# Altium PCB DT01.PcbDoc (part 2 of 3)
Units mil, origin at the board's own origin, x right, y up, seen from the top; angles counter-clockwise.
Board outline 2134.7 x 2226.1 mil, 2 copper layers (Top Layer, Bottom Layer), stack 57.918 mil thick; 95 components, 87 nets, 468 pads, 300 vias.
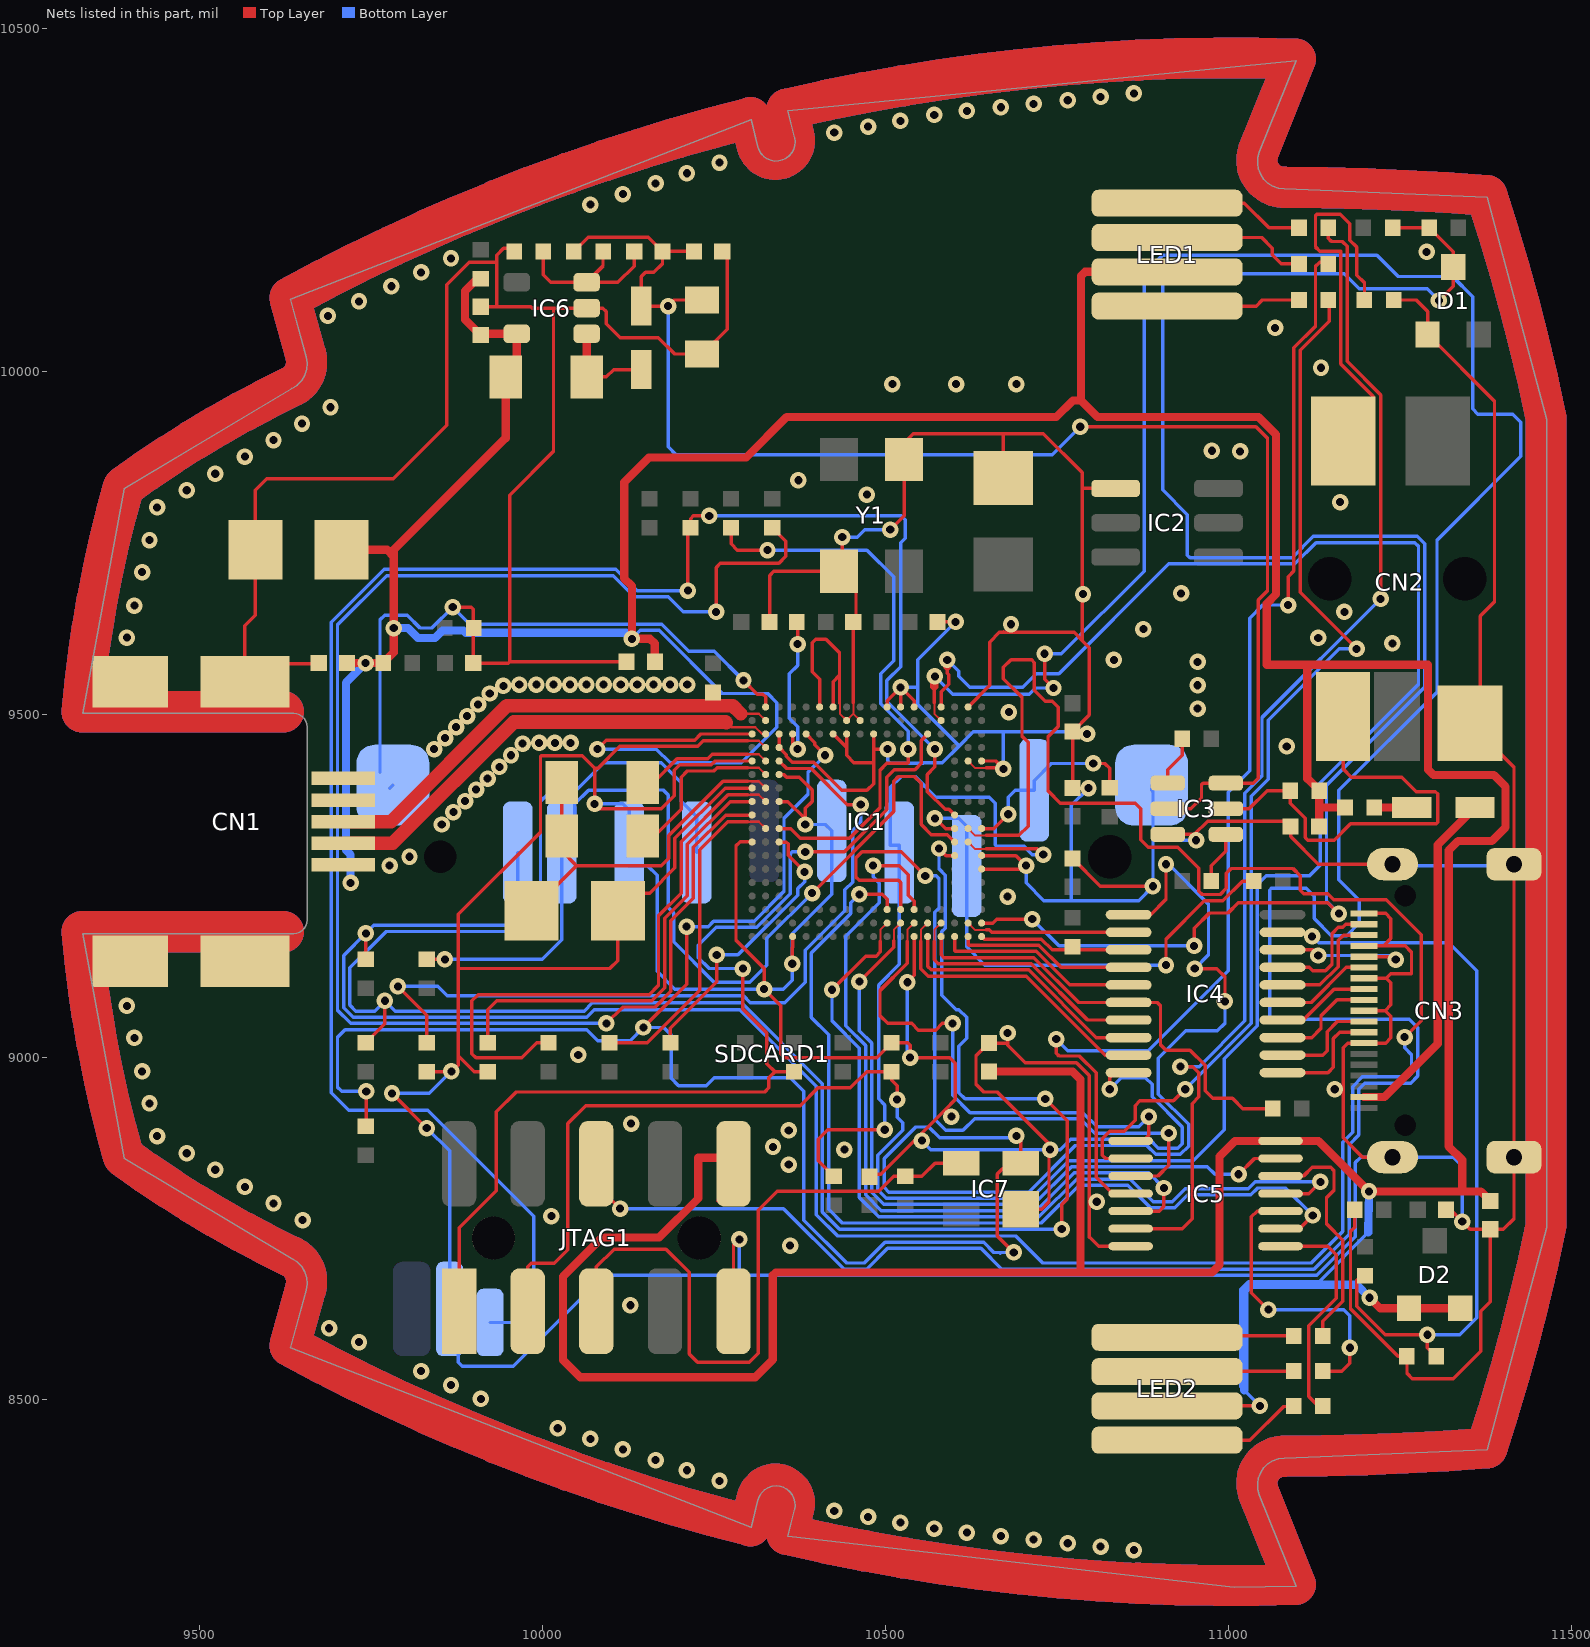
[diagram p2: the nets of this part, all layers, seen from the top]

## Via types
v1: diameter 24, hole 11.81, Top Layer to Bottom Layer, tented both sides, 295 vias
v2: diameter 24.02, hole 11.81, Top Layer to Bottom Layer, tented both sides, 5 vias

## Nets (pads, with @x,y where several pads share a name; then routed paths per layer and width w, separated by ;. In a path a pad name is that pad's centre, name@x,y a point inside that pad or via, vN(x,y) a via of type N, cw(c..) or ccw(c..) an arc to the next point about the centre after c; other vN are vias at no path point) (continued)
5V0: C15.2 C16.2 C17.2 C18.2 C19.1 C20.1 C21.1 CN1.1 D2.1 D2.2 IC1.T18 IC5.14 IC6.5 JTAG1.10 L3.1 LED1.A LED2.A R18.2 R20.2 R37.1 R42.1 | length 9669.8
  Top Layer w5: CN1.1@9709.36,9280.11 CN1.1@9710.34,9279.12 ; C18.2@9713.01,9572.3 C18.2@9715.04,9574.34 ; R42.1@9909.38,10134.7 R42.1@9909.87,10134.7 ; C15.2@9909.67,10052.76 C15.2@9909.87,10052.56 ; v1(10080.01,9449.02) 10093.01,9462.02 10222.01,9462.02 10230.91,9470.92 IC1.T18@10305.52,9470.92 ; JTAG1.10@10255.25,8790.07 10278.38,8813.21 JTAG1.10@10278.38,8844.21 10278.38,8849.02 JTAG1.10@10278.39,8900.76 ; JTAG1.10@10270.01,8790.07 JTAG1.10@10278.38,8798.45 ; LED2.A@10910.6,8491.32 v1(11045.79,8491.32) ; C20.1@11132,9336.21 11132.51,9336.72 11132.51,9363.74 ; 11132.53,9363.76 R20.2@11132.53,9388.34
  Top Layer w12: C19.1@9707.18,9739.65 9773.15,9739.65 9783.01,9729.79 ; C18.2@9715.04,9574.34 v1(9742,9574.34) R18.2@9767.66,9574.34 9783.01,9589.69 v1@9783.01,9625 ; v1(9783.01,9625.49) 9783.01,9729.79 ; R42.1@9909.38,10134.7 9904.69,10134.7 9887.01,10117.02 9887.01,10075.02 9909.47,10052.56 9909.67,10052.76 9911.44,10054.53 IC6.5@9962.36,10054.53 9962.36,10007.65 L3.1@9946.26,9991.56 9946.27,9902.28 9783.01,9739.02 9783.01,9729.79 ; C21.1@10163.75,9576.31 10163.75,9602.85 10156.85,9609.74 v1(10130.28,9609.74) 10130.28,9686.72 10119,9698 10119,9838 10155,9874 10297,9874 10356,9933 10749,9933 10773.23,9957.23 10785,9957.23 ; JTAG1.10@10278.38,8844.21 JTAG1.10@10269.59,8853 ; JTAG1.10@10278.39,8849.02 10274.4,8853 JTAG1.10@10269.59,8853 ; C16.2@10650.82,8979.01 10772.99,8979.01 10784.51,8967.49 10784.51,8686.49 ; LED1.A@10910.6,10144.87 10790.87,10144.87 10785,10139 10785,9957.23 ; C20.1@11132,9336.21 11132.51,9336.72 11132.51,9363.74 ; 11132.51,9363.78 R20.2@11132.51,9388.36 11115,9405.88 11115,9572 ; 11132.53,9363.76 11132.77,9364 R37.1@11169.99,9364 ; v1(11206,8649) 11221.41,8633.59 D2.1@11263.33,8633.59 D2.2@11338.13,8633.59 ; 11341,8805 11341,8850 11321.19,8869.81 11321.19,9301.19 11335,9315 11384,9315 11403.86,9334.86 11403.86,9394.14 11387,9411 11299,9411 11291,9419 11291,9572 11115,9572 ; C17.2@11381.93,8790.08 11368.01,8804 v1(11205,8804) 11131.34,8877.66 IC5.14@11075.97,8877.66 11009.66,8877.66 10987,8855 10987,8697 10976,8686 10340.07,8686 10335.79,8681.72 10335.79,8558.79 10310,8533 10055,8533 10030,8558 10030,8680 10087,8737 10170,8737 10227,8794 10227,8853 JTAG1.10@10269.59,8853 ; 10785,9957.23 10809.23,9933 11044,9933 11069.51,9907.49 11069.51,9674.71 11056,9661.21 11056,9572 11115,9572
  Bottom Layer w5: v1(10080.01,9449.02) 10165.73,9449.02 10185.92,9428.83 10289.9,9428.83 10341.7,9480.63 10341.7,9516.41 10328.06,9530.04 10262.26,9530.04 10170.29,9622.02 10142.55,9622.02 v1(10130.28,9609.74) ; v1(11045.79,8491.32) 11023,8514.11 11017.85,8519.26 11017.85,8661.17 11029.31,8672.63 11132.23,8672.63 11203.82,8744.22
  Bottom Layer w12: v1(9720,9254) 9720,9295 9713.5,9301.5 9713.5,9545.84 v1(9742,9574.34) ; v1(9783.01,9625.49) 9803.63,9625.49 9818.11,9611 9842.98,9611 9854,9622.02 9884.63,9622.02 9888.13,9618.52 10121.51,9618.52 v1(10130.28,9609.74) ; 11023,8514.11 11023,8659 11032,8668 11187,8668 v1(11206,8649) ; 11203.82,8744.22 v1(11205,8804)
12V: C4.2 C5.2 C6.2 D4.2 IC3.2 IC3.6 R40.2 | length 2174.7
  Top Layer w5: R40.2@10045.81,10174.58 10066.45,10195.22 10154.25,10195.22 C6.2@10174.89,10174.58 ; C5.2@10222.94,10174.58 C5.2@10220.81,10174.58 C6.2@10174.89,10174.58 ; C4.2@10232.62,10103.74 10191.86,10103.74 v1(10183.01,10094.89) D4.2@10144.06,10094.89 10144.06,10138 10150.06,10144 10162,10144 10174.89,10156.89 C6.2@10174.89,10174.58 ; v1(10784.01,9919.02) 11040.28,9919.02 11057.01,9902.29 11057.01,9679.89 11043.5,9666.38 11043.5,9406.52 11036,9399.02 IC3.6@10996.58,9399.02 ; IC3.2@10895.97,9361.98 IC3.2@10911.57,9361.98 10945.24,9361.98 10960.78,9377.52 10960.78,9397.16 10963.01,9399.39 IC3.6@10996.22,9399.39
  Bottom Layer w5: v1@10181.45,10093.33 v1(10183.01,10094.89) 10183.01,9889.61 10194.6,9878.02 10743.01,9878.02 v1(10784.01,9919.02)
CARD_DET: IC1.K3 R22.1 SDCARD1.SW3 | length 2746.8
  Top Layer w5: v1(10212.01,9680.02) 10212.01,9767.72 R22.1@10215.89,9771.61 10215.89,9784.9 10220.01,9789.02 v1(10243.01,9789.02) ; v1(10572.01,9449.02) 10572.01,9422.96 10561.01,9411.96 10561.01,9387.02 10587.01,9361.02 10592.59,9361.02 IC1.K3@10600.8,9352.81
  Bottom Layer w5: SDCARD1.SW3@9923.5,8612.95 9968.9,8612.95 9987.01,8631.05 9987.01,8768.03 9832.52,8922.52 9717.2,8922.52 9692,8947.72 9692,9634.14 9768.88,9711.02 10106.7,9711.02 10137.7,9680.02 v1(10212.01,9680.02) ; v1(10243.01,9789.02) 10523.01,9789.02 10528.8,9783.22 10528.8,9756.36 10522.01,9749.57 10522.01,9569.02 10502.01,9549.02 10502.01,9519.02 v1(10572.01,9449.02)
D+: CN1.3 IC1.U17 R16.1 | length 688.2
  Top Layer w3: 10295.71,9500.5 10315.32,9500.5 IC1.U17@10325.21,9490.61
  Top Layer w20: CN1.3@9709.38,9343.1 9779.01,9343.1 9948.24,9512.33 10248.36,9512.33 10277.12,9512.33 10288.95,9500.5
D-: CN1.2 IC1.T17 | length 698.2
  Top Layer w3: 10268.01,9487.5 10274.69,9480.81 10310.4,9480.81 10320.29,9470.92 IC1.T17@10325.21,9470.92 IC1.T17@10327.18,9470.92
  Top Layer w20: CN1.2@9709.38,9311.6 9781.46,9311.6 9958.18,9488.33 10267.18,9488.33 10268.01,9487.5
GND: C1.2 C2.1 C3.2 C4.1 C5.1 C7.1 C8.1 C9.1 C10.2 C11.2 C12.2 C13.2 C14.2 C15.1 C16.1 C17.1 C18.1 C19.2 C20.2 C21.2 CN1.4 CN1.5 CN1.MH1 CN1.MH2 CN1.MH3 CN1.MH4 CN2.1 CN3.1 CN3.4 CN3.7 CN3.10 CN3.13 CN3.MH1 CN3.MH2 CN3.MH3 CN3.MH4 D1.1 IC1.A6 IC1.A15 IC1.F1 IC1.G1 IC1.H18 IC1.L16 IC1.M18 IC1.N16 IC1.P1 IC1.P2 IC1.P18 IC1.R16 IC1.R17 IC1.T9 IC1.T11 IC1.T12 IC1.T16 IC1.U10 IC1.U11 IC1.V2 IC1.V6 IC1.V7 IC1.V8 IC1.V12 IC1.V13 IC1.V17 IC2.1 IC3.3 IC4.10 IC5.7 IC6.2 IC7.1 JTAG1.9 JTAG1.PEGA JTAG1.PEGB R4.2 R6.2 R15.2 R17.2 R19.2 R21.2 R32.1 R45.1 SDCARD1.3 SDCARD1.6 SDCARD1.MH1 SDCARD1.MH2 SDCARD1.SW1 Y1.2 Y1.4 | length 35773.3
  Top Layer w3: 10299.03,9461.13 10315.32,9461.13 IC1.R17@10325.21,9451.24 ; 10433.43,9515.92 10433.43,9500.5 IC1.U11@10443.27,9490.66 ; IC1.U11@10443.22,9490.61 IC1.U11@10443.27,9490.66 ; IC1.U11@10443.32,9490.61 IC1.U11@10443.27,9490.66 ; 10453.11,9516.82 10453.11,9500.5 ; IC1.U10@10463,9490.61 10453.11,9500.5 ; IC1.P2@10620.48,9431.55 10630.37,9421.66 10646.66,9421.66 ; IC1.U11@10443.27,9490.66 10453.11,9500.5
  Top Layer w5: CN1.MH3@9398.64,9139.36 9398.64,9171.02 CN1.MH4@9565.96,9171.02 ; CN1.MH2@9398.64,9546.84 9398.64,9515.02 CN1.MH1@9565.96,9515.02 ; CN1.MH4@9565.96,9139.36 CN1.MH4@9566.3,9139.02 ; C18.1@9673.7,9574.34 9673.01,9573.64 9592.77,9573.64 CN1.MH1@9565.96,9546.84 9565.97,9629.02 9581.2,9644.25 C19.2@9581.2,9739.65 9581.2,9826.2 9598,9843 9782,9843 9860,9921 9860,10126.02 9893,10159.02 9933.01,10159.02 ; v1(9780.49,8947) v1(9831.14,8896.34) ; R4.2@9831.15,8978.5 9867,8978.5 9867.5,8978.5 9877.01,8988.01 9877.01,9002.02 ; v1(9869.01,9656.02) 9896.06,9656.02 9899.05,9653.03 9899.05,9625.51 C2.1@9899.05,9574.34 9950.21,9574.34 9952.18,9576.31 ; C15.1@9909.87,10093.9 9933.01,10093.9 ; R6.2@9919.96,8978.5 9900.52,8978.5 9877.01,9002.02 ; R45.1@9958.55,10174.58 9958.55,10179.02 9943.01,10179.02 9933.01,10169.02 9933.01,10159.02 ; IC6.2@10053.01,10092.03 10016,10092.03 ; IC6.2@10064.36,10092.03 10088.01,10092.03 10093.01,10087.03 10093.01,10069.02 10113.01,10049.02 10168.66,10049.02 10192.67,10025 C4.1@10232.62,10025 10269.02,10061.4 10269.02,10167.7 C5.1@10262.15,10174.58 ; C1.2@10109.64,9213.21 10109.64,9140.4 10098.26,9129.02 9878.52,9129.02 9877.01,9130.54 ; C21.2@10122.41,9576.31 9952.18,9576.31 ; C1.2@10129.64,9239.02 10156.01,9239.02 10193.01,9276.02 10193.01,9319.02 10266.17,9392.18 IC1.M18@10305.52,9392.18 ; JTAG1.9@10278.38,8629.21 10278.38,8725.38 v1(10287,8734) ; v1(10293.01,9549.02) 10312.97,9529.06 10321.18,9529.06 10325.21,9525.02 IC1.V17@10325.21,9510.29 IC1.V17@10323.01,9510.29 ; 10299.03,9461.13 10234.12,9461.13 10226.01,9453.02 10112.8,9453.02 10080.8,9421.02 10076.01,9421.02 ; IC1.P18@10305.52,9431.55 10251.54,9431.55 10246.01,9426.02 10200.01,9426.02 10192.01,9418.02 10192.01,9381.02 10173.01,9362.02 10083.01,9362.02 v1(10076.01,9369.02) 10076.01,9421.02 ; IC1.H18@10305.52,9313.44 10303.01,9313.44 10303.01,9314.02 10288.01,9314.02 10282.01,9308.02 10282.01,9170.02 10323.01,9129.02 v1(10323.01,9099.02) 10347.01,9075.02 10347.01,9005.02 10353.01,8999.02 10487.03,8999.02 R15.2@10508.88,9020.86 10532.2,9020.86 10536.01,9017.06 v1(10536.01,8999.02) 10594.01,8999.02 10602.01,8991.02 10602.01,8938.02 10586.49,8922.51 10547.49,8883.51 10493.01,8829.02 10476.65,8829.02 C9.1@10476.65,8825.52 ; C12.2@10331.03,9634.36 10331.03,9702.03 10337.34,9708.34 Y1.2@10432.1,9708.33 10437.01,9713.24 v1(10437.01,9758.02) ; IC1.T16@10343.01,9470.92 IC1.T16@10344.89,9470.92 IC1.R16@10344.89,9451.24 ; IC1.L16@10344.89,9372.5 10357.68,9372.5 v1@10383.01,9347.17 ; IC1.N16@10344.89,9411.87 10351.85,9411.87 10355.7,9408.02 10374.32,9408.02 10393.01,9389.33 10393.01,9372.6 10383.01,9362.6 v1@10383.01,9347.17 ; IC1.R16@10344.9,9449.13 IC1.R16@10344.89,9451.24 ; v1(10364.01,9136.02) 10364.01,9159.49 ; 10364.58,9160.06 IC1.A15@10364.58,9175.65 ; v1(10383.01,9339.02) v1@10383.01,9347.17 ; IC1.V13@10403.95,9510.29 10404.01,9510.29 10404.01,9550.75 10393.01,9561.75 10393.01,9604.01 10398.14,9609.14 10413.23,9609.14 10433.01,9589.36 10433.01,9556.61 ; IC1.T12@10423.63,9469.02 10423.01,9469.02 10423.01,9470.92 IC1.T12@10423.63,9470.92 10443.32,9451.24 ; IC1.V12@10423.63,9510.29 10423.63,9547.24 10433.01,9556.61 ; 10433.01,9515.92 10433.01,9556.61 ; IC1.T11@10443.01,9470.92 IC1.T11@10443.32,9470.92 10443.32,9451.24 ; C13.2@10453.03,9634.36 10453.03,9516.9 10453.11,9516.82 ; C13.2@10457.01,9639.02 Y1.2@10457.01,9708.33 ; 10482.01,9429.02 10454.01,9429.02 10443.32,9439.71 10443.32,9451.24 ; IC1.V8@10502.01,9509.02 IC1.V8@10502.37,9509.02 ; IC1.V8@10502.37,9510.29 10502.38,9519.39 v1(10522.01,9539.02) ; v1(10503.01,9449.02) 10482.69,9449.02 ; v1(10507.01,9769.02) 10527.11,9789.12 Y1.4@10527.1,9871.33 ; IC1.V7@10522.06,9510.29 10522.06,9538.97 10541.74,9519.28 IC1.V6@10541.74,9510.29 ; Y1.4@10527.11,9895.52 10540.61,9909.02 10673.45,9909.02 ; v1(10532.01,9109.02) 10542.01,9119.02 IC1.A6@10542.01,9175.65 ; IC1.A6@10541.74,9176.13 IC1.A6@10541.98,9175.89 ; C14.2@10574.01,9632.32 C14.2@10576.04,9634.36 v1(10602.35,9634.36) ; IC1.V2@10620.48,9510.29 10652.01,9541.81 10652.01,9605.02 10666.01,9619.02 10683,9619.02 10775.01,9619.02 10787.01,9607.02 ; IC1.F1@10640.17,9274.07 10700.06,9274.07 v1(10705.01,9279.02) 10690.27,9293.76 IC1.G1@10640.17,9293.76 ; IC1.P1@10640.17,9431.55 10660.47,9431.55 v1@10670.27,9421.76 ; IC1.G1@10641.96,9291.97 IC1.G1@10643.01,9293.02 ; 10646.66,9421.66 v1@10670.36,9421.66 ; C10.2@10671.49,9843.97 10671.49,9907.06 10673.45,9909.02 ; 10672.04,9620.04 ccw(c10674.5,9622.5) 10674.5,9619.02 ; v1(10678,9035) 10678,9020.35 ; IC7.1@10697.08,8778.28 10727.58,8778.27 10738.39,8789.09 10738.39,8865 10738.39,8873.63 10663.01,8949.02 10643.01,8949.02 10632.01,8960.02 10632.01,9001.54 C16.1@10650.82,9020.35 10678,9020.35 ; C11.2@10772.84,9288.18 C11.2@10772.84,9289.49 10813.31,9249.02 v1(10890.01,9249.02) ; C8.1@10772.84,9392.31 C7.1@10772.84,9474.46 10797.01,9498.63 10797.01,9597.02 10787.01,9607.02 ; v1(10827,8953) 10827,8970 10834.17,8977.17 IC4.10@10854.51,8977.17 ; IC2.1@10835.6,9829.01 10787.01,9829.01 ; IC2.1@10835.6,9830.16 10841.71,9830.16 IC2.1@10840.56,9829.01 ; IC5.7@10857.46,8724.12 10810.88,8724.12 10798.01,8736.99 10797.01,8736.99 10797.01,8789 10797.01,8973 10778.49,8991.51 10703.5,8991.51 10678,9017.01 10678,9020.35 ; IC3.3@10916,9329.01 IC3.3@10911.57,9324.58 10950.19,9324.58 10969.63,9344.02 11082.86,9344.02 C20.2@11090.66,9336.21 11090.66,9321.5 11131,9281.16 CN3.MH4@11239.2,9281.16 ; R21.2@11184.01,8777.18 11184.01,8752.01 11178,8746 11178,8633 11247.25,8563.75 R32.1@11260.38,8563.75 11260.38,8538.62 11268,8531 11328,8531 11368,8571 11368,8629 11382,8643 C17.1@11382,8748.74 ; CN3.10@11197.86,9067.58 11228.57,9067.58 ; CN3.7@11197.86,9114.82 11230.42,9114.82 ; CN3.4@11197.86,9162.07 11226.22,9162.07 ; CN3.1@11197.86,9209.02 11193.01,9209.02 11193.01,9209.31 CN3.1@11197.86,9209.31 11229.35,9209.31 11237.01,9201.66 11237.01,9172.85 11226.22,9162.07 ; CN3.MH1@11239.2,8854 11195.48,8854 11167.5,8881.98 11167.5,8953 11167.5,9013.51 11174.32,9020.33 CN3.13@11197.86,9020.33 11229.14,9020.33 11237.01,9028.2 11237.01,9059.14 11228.57,9067.58 ; R19.2@11240.75,10103.73 11273.67,10103.73 11290.41,10086.99 D1.1@11290.41,10053.53 11388.01,9955.94 11388.01,9664.02 11367.01,9643.02 CN2.1@11367.01,9489.02 ; C3.2@11317.37,8777.18 11323.82,8777.18 v1(11341,8760) 11352.26,8748.74 C17.1@11381.93,8748.74 C17.1@11382,8748.74 ; CN2.1@11352.38,9489.02 CN2.1@11352.38,9486.71 11416.36,9422.73 CN3.MH3@11416.36,9281.16 CN3.MH2@11416.36,8854 11416.36,8764.36 11400.74,8748.74 C17.1@11382,8748.74 ; 9877.01,9002.02 9877.01,9130.54 ; 9877.01,9130.54 9877.01,9208.02 9997.01,9328.02 9997.01,9438.02 9998.01,9439.02 10058.01,9439.02 10076.01,9421.02 ; 9933.01,10093.9 9933.01,10159.02 ; 9933.01,10093.9 9983.01,10093.9 9984.87,10092.03 10016,10092.03 ; 9952.18,9576.31 9952.18,9819.18 10016,9883 10016,10092.03 ; IC1.R16@10344.89,9451.24 10355.53,9440.6 10355.53,9438.49 10364.35,9429.67 10395.35,9429.67 10436.01,9389.02 10473.01,9389.02 10482.69,9398.7 10482.69,9449.02 ; 10482.69,9449.02 IC1.T9@10482.69,9469.34 ; IC1.T9@10482.69,9469.34 IC1.T9@10482.69,9470.92 IC1.T9@10482.69,9469.34 ; 10673.45,9909.02 10730.28,9909.02 10787.01,9852.29 10787.01,9829.01 ; 10787.01,9607.02 10787.01,9675 10787.01,9829.01 ; 11226.22,9162.07 11257.93,9162.07 11267,9153 11267,9121 11266.59,9121.41 11237.01,9121.41 11230.42,9114.82 ; 11228.57,9067.58 11236.91,9075.92 11236.91,9108.34 11230.42,9114.82
  Top Layer w60: 9622,9182.61 9565.96,9182.61 9398.64,9182.61 9328.42,9182.61 ccw(c11116.51,9343.04) 9388.86,8854.97 ccw(c10303.51,10107.8) 9633.7,8708.68 cw(c9616.7,8673.17) 9654.65,8662.69 9631.51,8578.94 ccw(c11007.41,11111.18) 10303.15,8316.66 10312.86,8356.21 cw(c10339.63,8349.64) 10366.39,8343.07 10356.73,8303.7 ccw(c11007.41,11111.18) 11097.83,8230.7 11044.32,8363.83 cw(c11080.85,8378.51) 11080.68,8417.88 ccw(c11063.75,12502.73) 11376.58,8429.84 ccw(c8605.87,9343.04) 11463.13,8754.11 11463.13,8854 11463.13,9281.16 11463.13,9931.98 ccw(c8605.87,9343.04) 11376.58,10256.24 ccw(c11063.75,6183.36) 11080.68,10268.2 cw(c11080.85,10307.57) 11044.32,10322.26 11097.83,10455.38 ccw(c11007.41,7574.91) 10356.73,10382.38 10366.39,10343.02 cw(c10339.63,10336.45) 10312.86,10329.88 10303.15,10369.43 ccw(c11007.41,7574.91) 9631.51,10107.14 9654.65,10023.4 cw(c9616.7,10012.92) 9633.7,9977.41 ccw(c10303.51,8578.29) 9388.86,9831.12 ccw(c11116.51,9343.04) 9328.42,9503.48 9398.64,9503.48 9565.96,9503.48 9622,9503.48
  Bottom Layer w5: SDCARD1.MH2@9763.01,9415.18 9763.01,9637.3 9769.89,9644.18 9802.61,9644.18 9821.3,9625.49 9838.47,9625.49 v1(9869.01,9656.02) 9894.01,9631.02 10174.01,9631.02 10213.14,9591.89 10250.14,9591.89 v1(10293.01,9549.02) ; SDCARD1.MH2@9777.01,9391.64 SDCARD1.MH2@9781.77,9396.41 ; v1(9780.49,8947) 9835,8947 v1(9867,8979) ; v1(9831.14,8896.34) 9864.45,8863.04 SDCARD1.SW1@9864.45,8632.63 ; SDCARD1.SW1@9877.01,8632.63 9877.01,8555.02 9883.01,8549.02 9957.12,8549.02 10089.73,8681.63 10287,8681.63 ; v1(10076.01,9369.02) 10117.13,9369.02 10126.34,9359.81 10126.26,9359.72 SDCARD1.6@10126.26,9298.18 SDCARD1.6@10126.34,9298.27 ; SDCARD1.6@10126.26,9279.02 10153.01,9279.02 10167.01,9265.02 10167.01,9125.02 10193.01,9099.02 v1(10323.01,9099.02) 10351.18,9099.02 10364.01,9111.84 v1(10364.01,9136.02) 10364.01,9179.75 10421.54,9237.28 SDCARD1.3@10421.54,9329.68 10412.2,9339.02 v1(10383.01,9339.02) ; v1(10287,8734) 10287,8681.63 ; v1(10437.01,9758.02) 10458.6,9758.02 10469.6,9769.02 v1(10507.01,9769.02) ; v1(10503.01,9449.02) 10503.01,9431.75 10506.73,9428.02 10555,9428.02 10556,9429.02 10583.01,9429.02 10607.51,9453.52 ; v1(10522.01,9539.02) 10547.01,9539.02 ; v1(10532.01,9109.02) 10532.01,9003.02 v1(10536.01,8999.02) ; v1(10553,8878) 10566,8865 v1(10740,8865) 10755,8865 10770.02,8880.02 10884.98,8880.02 10897.98,8867.02 10926.29,8867.02 10933,8873.73 10933,8898 10889,8942 10889,8960.02 10879,8970.02 10844.02,8970.02 v1(10827,8953) ; v1(10602.35,9634.36) 10547.01,9579.02 10547.01,9539.02 ; v1(10672.01,9420.02) 10672.01,9474.02 ; v1(10705.01,9279.02) 10705.01,9254 10730.99,9228.02 10771,9228.02 ; v1(10794,9471) 10790.98,9474.02 10672.01,9474.02 ; v1(10796,9392) 10771,9367 10771,9228.02 ; SDCARD1.MH1@10888.07,9396.41 10888.07,9389.02 10890.01,9387.08 v1(10890.01,9249.02) 10869.01,9228.02 10771,9228.02 ; 10892.01,9316 v1(10953,9316) ; 11185.01,8845.18 11185.01,8738.13 11128.5,8681.63 10287,8681.63 ; 11185.01,8846.16 11192.84,8854 CN3.MH1@11239.2,8854 11328,8854 11341,8841 v1(11341,8760) ; CN3.MH4@11239.2,9281.16 11243.01,9281.16 11243.01,9279.02 11413.01,9279.02 11413.01,9281.16 CN3.MH3@11416.36,9281.16 ; 10547.01,9539.02 10547.01,9514.02 10607.51,9453.52 ; 10607.51,9453.52 10628.01,9474.02 10672.01,9474.02
  Bottom Layer w60: 9622,9182.61 9366.52,9182.61 9328.42,9182.61 ccw(c11116.51,9343.04) 9388.86,8854.97 ccw(c10303.51,10107.8) 9633.7,8708.68 cw(c9616.7,8673.17) 9654.65,8662.69 9631.51,8578.94 ccw(c11007.41,11111.18) 10303.15,8316.66 10312.86,8356.21 cw(c10339.63,8349.64) 10366.39,8343.07 10356.73,8303.7 ccw(c11007.41,11111.18) 11097.83,8230.7 11044.32,8363.83 cw(c11080.85,8378.51) 11080.68,8417.88 ccw(c11063.75,12502.73) 11376.58,8429.84 ccw(c8605.87,9343.04) 11463.13,8754.11 11463.13,8854 11463.13,9281.16 11463.13,9931.98 ccw(c8605.87,9343.04) 11376.58,10256.24 ccw(c11063.75,6183.36) 11080.68,10268.2 cw(c11080.85,10307.57) 11044.32,10322.26 11097.83,10455.38 ccw(c11007.41,7574.91) 10356.73,10382.38 10366.39,10343.02 cw(c10339.63,10336.45) 10312.86,10329.88 10303.15,10369.43 ccw(c11007.41,7574.91) 9631.51,10107.14 9654.65,10023.4 cw(c9616.7,10012.92) 9633.7,9977.41 ccw(c10303.51,8578.29) 9388.86,9831.12 ccw(c11116.51,9343.04) 9328.42,9503.48 9366.52,9503.48 9622,9503.48
  other v1: 10862.29,8280.95 10813.56,8286.07 10765.82,8291.09 10716.09,8296.32 10668.36,8301.33 10618.63,8306.56 10571.06,8312.46 10521.82,8321.14 10474.55,8329.47 10425.31,8338.16 10258,8382.09 10210.45,8397.54 10164.8,8412.37 10117.24,8427.82 10069.69,8443.27 10022.14,8458.72 9910.01,8501.43 9866.5,8521.71 9823,8542 9732.37,8584.26 9688.87,8604.55 10128,8638 9650.11,8762.15 10013,8768 9607.67,8786.65 10808,8789 9566.1,8810.65 9522.8,8835.65 10359,8843 9481.23,8859.65 10440,8865 10336,8869 9437.93,8884.65 10359,8893 10129,8903 10596,8913 9426.91,8932.39 11155,8953 9416.11,8979.16 10052,9003 9404.86,9027.88 9394.07,9074.65 10678,9234 9777.02,9279.12 9806,9292 9853,9339 9870,9357 9887,9373 9903,9390 9920,9406 9937,9423 9954,9440 9842,9449 11085,9453 9971,9457 9995,9458 10018,9458 10041,9458 9858,9465 9874,9481 9890,9497 10680,9503 10955,9508 9906,9514 9923,9530 9943,9541 10955,9542 9966,9543 9991,9543 10016,9543 10040,9543 10064,9543 10089,9543 10114,9543 10138,9543 10162,9543 10186,9543 10211,9543 10955,9576 10833,9579 11239,9603 9394.07,9611.44 11131,9611 10876,9624 10683,9631 11169,9649 9404.86,9658.21 10788,9675 10931,9676 9416.11,9706.93 9426.91,9753.7 9437.93,9801.44 11163,9809 10473,9820 9481.23,9826.44 10373,9841 9522.8,9850.44 9566.1,9875.44 11017,9883 10976,9884 9607.67,9899.44 9649.24,9923.44 9690.81,9947.44 10510,9981 10603,9981 10691,9981 11135,10005 11068,10063 9687.05,10080.69 9732.37,10101.82 9779.5,10123.8 9823,10144.09 9866.5,10164.37 11289,10174 10069.69,10242.81 10117.24,10258.27 10164.8,10273.72 10210.45,10288.55 10258,10304 10425.31,10347.93 10474.55,10356.61 10521.82,10364.95 10571.06,10373.63 10618.63,10379.53 10668.36,10384.75 10716.09,10389.77 10765.82,10395 10813.56,10400.01 10862.29,10405.14
  other v2: 10360.98,8725
HARD.TCK: CN3.6 IC4.15 | length 140.1
  Top Layer w5: IC4.15@11078.92,9079.53 11120.53,9079.53 11171.57,9130.57 CN3.6@11197.86,9130.57
HARD.TDI: CN3.9 IC4.13 | length 152.3
  Top Layer w5: IC4.13@11078.92,9028.35 11121.36,9028.35 11135.01,9042 11135.01,9060.01 11158.33,9083.33 CN3.9@11197.86,9083.33
HARD.TDO: CN3.8 IC4.14 | length 148
  Top Layer w5: IC4.14@11078.92,9053.94 11108.92,9053.94 11154,9099.02 11197.86,9099.02 11203.01,9099.02 11203.01,9099.07 CN3.8@11197.86,9099.08
HARD.TMS: CN3.5 IC4.18 | length 218.9
  Top Layer w5: IC4.18@11078.92,9156.3 11122.7,9156.3 v1(11131,9148) ; CN3.5@11197.86,9146.32 11239.68,9146.32 v1(11244,9142)
  Bottom Layer w5: v1(11131,9148) 11238,9148 v1(11244,9142)
JTSEL: IC1.U4 JTAG1.6 | length 4768.3
  Top Layer w3: 10571.22,9516.79 10571.22,9500.5 IC1.U4@10581.11,9490.61
  Top Layer w5: JTAG1.6@10078.38,8844.21 10078.38,8849.02 10087.01,8849.02 10087.01,8844.21 10087.01,8805.02 v1(10113.01,8779.02) ; 10571.22,9516.79 10571.22,9540.26 ; v1(10732.01,9588.02) 10732.01,9551.02 v1(10745.01,9538.02)
  Top Layer w12: 10571.22,9540.26 10571.22,9554.24 v1(10572.01,9555.02)
  Bottom Layer w5: v1(10113.01,8779.02) 10351.29,8779.02 10439.68,8690.63 10472.59,8690.63 10502.98,8721.02 10639.27,8721.02 10669.67,8690.63 11124.77,8690.63 11176.01,8741.86 11176.01,8872.29 11190.01,8886.29 11190.01,8953 11199.01,8962 11265.71,8962 11276.01,8972.29 11276.01,9042.61 11263.85,9054.77 11060,9054.77 11060,9243.27 11062.73,9246 11113.27,9246 11125,9234.27 11125,9202 11150,9177 11172.32,9177 11191.01,9195.69 11191.01,9228.73 11161.01,9258.73 11161.01,9388.83 11304.19,9532.02 11304.19,9753.59 11426.5,9875.91 11426.5,9925.52 11414.61,9937.42 11363.54,9937.42 11356.01,9944.95 11356.01,10108.75 11326.73,10138.02 11247.62,10138.02 11216.62,10169.02 10903.9,10169.02 10877.01,10142.13 10877.01,9708.47 10756.55,9588.02 v1(10732.01,9588.02) ; v1(10572.01,9555.02) 10598.01,9529.02 10709.86,9529.02 10718.86,9538.02 v1(10745.01,9538.02)
LED1.BLU: IC1.C7 IC5.3 | length 1102.2
  Top Layer w5: IC1.C7@10522.01,9215.02 10522.01,9254.43 10518.96,9257.47 10461.89,9257.47 10457.01,9262.35 10457.01,9290.29 10465.73,9299.02 10523.01,9299.02 v1(10558.01,9264.02) ; IC5.3@10857.46,8826.48 10897.32,8826.48 10913.01,8842.16 v1(10913.01,8889.02)
  Bottom Layer w5: v1(10558.01,9264.02) 10573.99,9264.02 10578.01,9260 10578.01,9217.02 10572.01,9211.02 10572.01,8908.99 10588,8893 10612.98,8893 10630,8910.02 10784,8910.02 10805,8889.02 v1(10913.01,8889.02)
LED1.GRN: IC1.B6 IC5.1 | length 754.3
  Top Layer w3: 10531.85,9165.84 10531.85,9185.44 IC1.B6@10541.74,9195.33
  Top Layer w5: 10531.85,9165.84 10531.85,9169.02 ; 10532.01,9169.02 10532.01,9137.02 10492.01,9097.02 10492.01,9060.02 10503.01,9049.02 10538.01,9049.02 10548.01,9039.02 10573.08,9039.02 10583.08,9049.02 v1(10598.01,9049.02) ; IC5.1@10857.46,8877.66 10875.66,8877.66 10884,8886 v1(10884,8913)
  Bottom Layer w5: v1(10598.01,9049.02) 10598.01,8944.23 10623.22,8919.02 10787.73,8919.02 10808.73,8898.02 10869.02,8898.02 v1(10884,8913)
LED1.RED: IC1.C6 IC5.5 | length 1181.9
  Top Layer w5: v1(10482.01,9279.02) 10520.05,9279.02 10533.27,9265.79 10533.27,9235.67 10541.74,9227.2 IC1.C6@10541.74,9215.02 ; IC5.5@10857.46,8775.3 10899.3,8775.3 10906.01,8782.01 v1(10906.01,8809.02)
  Bottom Layer w5: v1(10482.01,9279.02) 10482.01,9262.75 10491.01,9253.75 10491.01,9225.21 10442.01,9176.21 10442.01,9045.75 10471.01,9016.75 10471.01,8798.88 10493.86,8776.02 10719.94,8776.02 10774.94,8831.02 10884.01,8831.02 v1(10906.01,8809.02)
LED2.BLU: IC1.B8 IC5.11 | length 1256.2
  Top Layer w3: 10492.48,9169.16 10492.48,9185.44 IC1.B8@10502.37,9195.33
  Top Layer w5: v1(10422.01,9098.02) 10471.22,9147.23 10486.49,9147.23 10492.48,9153.22 10492.48,9169.16 ; IC5.11@11075.97,8800.89 11116.87,8800.89 v1(11134.01,8818.02)
  Bottom Layer w5: v1(10422.01,9098.02) 10422.01,9053.02 10462.01,9013.02 10462.01,8795.15 10490.14,8767.02 10723.66,8767.02 10778.66,8822.02 10857.17,8822.02 10890.17,8789.02 10918,8789.02 10936.98,8808 11028.89,8808 11038.91,8818.02 v1(11134.01,8818.02)
LED2.GRN: IC1.C8 IC5.9 | length 1392.2
  Top Layer w5: v1(10462.01,9237.02) 10495.27,9237.02 10502.37,9229.92 IC1.C8@10502.37,9215.02 ; IC1.C8@10502.37,9215.02 10503.01,9215.02 IC1.C8@10502.69,9215.33 ; IC5.9@11075.97,8749.71 11103.69,8749.71 v1(11123.01,8769.02)
  Bottom Layer w5: v1(10462.01,9237.02) 10449.64,9224.65 10449.64,9209.3 10392.01,9151.66 10392.01,9057.56 10417.01,9032.56 10417.01,8777.75 10436.73,8758.02 10727.39,8758.02 10782.39,8813.02 10853.44,8813.02 10886.44,8780.02 10921.73,8780.02 10940.71,8799 11032.62,8799 11042.63,8809.02 11083.01,8809.02 v1(11123.01,8769.02)
LED2.RED: IC1.B7 IC5.13 | length 1065.2
  Top Layer w3: 10512.17,9169.21 10512.17,9185.44 IC1.B7@10522.06,9195.33
  Top Layer w5: v1(10462.01,9110.02) 10512.17,9160.18 10512.17,9169.16 10512.23,9169.21 ; v1(11015.01,8829.02) 11038.06,8852.07 IC5.13@11075.97,8852.07
  Bottom Layer w5: v1(10462.01,9110.02) 10462.01,9038.47 10480.01,9020.47 10480.01,8802.61 10497.59,8785.02 10716.21,8785.02 10771.21,8840.02 10969.46,8840.02 10980.46,8829.02 v1(11015.01,8829.02)
MCLK: IC1.G3 R27.1 SDCARD1.5 | length 3013.2
  Top Layer w5: R27.1@9742.34,9020.86 9770,9048.52 v1(9770,9082) ; v1(10578.01,9304.02) 10588.27,9293.76 IC1.G3@10600.8,9293.76 ; v1(10733.01,8939.02) 10765,8907.02 10765,8792.99 10757.01,8785 v1(10757.01,8749.02)
  Bottom Layer w5: SDCARD1.5@10224.68,9298.18 10224.68,9350.03 10202.01,9372.71 10202.01,9400.02 10173.01,9429.02 10089.02,9429.02 10044,9384 10008.01,9384 9997.01,9373 9997.01,9196.02 9984,9183.02 9772.02,9183.02 9719,9130 9719,9075.85 9727.83,9067.02 9755.02,9067.02 v1(9770,9082) 9784.98,9067.02 10060.67,9067.02 10072.67,9079.02 10290.28,9079.02 10408.01,8961.29 10408.01,8774.02 10433.01,8749.02 v1(10757.01,8749.02) ; v1(10578.01,9304.02) 10578.01,9274.19 10587.01,9265.19 10587.01,9188.02 10582.01,9183.02 10582.01,9090.02 10603.01,9069.02 10607.05,9069.02 10618.34,9057.72 10618.34,9027.22 10607.01,9015.88 10607.01,8947.96 10615.95,8939.02 v1(10733.01,8939.02)
MCMD: IC1.H2 R26.1 SDCARD1.2 | length 1123.6
  Top Layer w3: IC1.H2@10620.48,9313.44 10630.37,9303.55 10646.66,9303.55
  Top Layer w5: R26.1@10424.49,8826.07 10402,8848.57 10402,8880 10416,8894 v1(10499,8894) ; 10646.66,9303.55 10721.47,9303.55 v1(10730.01,9295.02)
  Bottom Layer w5: v1(10499,8894) 10499,8930 10490,8939 10490,9105 10519.96,9134.96 SDCARD1.2@10519.96,9298.18 10519.96,9309.02 10507.01,9309.02 10507.01,9393.02 10523.01,9409.02 10543.01,9409.02 10573.01,9379.02 10651.01,9379.02 10660.01,9370.02 10660.01,9309.48 10661.86,9307.63 10701.68,9307.63 10714.29,9295.02 v1(10730.01,9295.02)
MCU_HARD.TCK: IC1.A3 IC4.5 | length 294.7
  Top Layer w5: IC1.A3@10600.8,9175.65 10600.8,9155.23 10601.2,9155.23 ; 10601.2,9154.82 10602.02,9154 10719.91,9154 10768.79,9105.12 IC4.5@10854.51,9105.12
MCU_HARD.TDI: IC1.B4 IC4.7 | length 377.2
  Top Layer w3: 10571.22,9169.16 10571.22,9185.44 IC1.B4@10581.11,9195.33
  Top Layer w5: 10571.22,9169.16 10571.22,9142 10577.22,9136 10712.46,9136 10794.51,9053.94 IC4.7@10854.51,9053.94
MCU_HARD.TDO: IC1.A4 IC4.6 R34.1 | length 657.8
  Top Layer w5: IC1.A4@10581.11,9175.65 10581.11,9148.91 10585.02,9145 10716.18,9145 10781.65,9079.53 IC4.6@10854.51,9079.53 10896,9079.53 10901,9074.53 10901,9018 10909,9010 10944,9010 10966,8988 10966,8951 10977.36,8939.64 11006,8939.64 11020.76,8924.88 R34.1@11064.56,8924.88
MCU_HARD.TMS: IC1.B2 IC4.2 | length 239.6
  Top Layer w3: IC1.B2@10620.48,9195.33 10630.37,9185.44 10646.66,9185.44
  Top Layer w5: 10646.66,9185.44 10651.56,9185.44 10655.11,9181.89 IC4.2@10854.51,9181.89
MCU_SOFT.TCK: IC1.B5 IC4.9 | length 425.7
  Top Layer w3: 10551.54,9169.16 10551.54,9185.44 IC1.B5@10561.43,9195.33
  Top Layer w5: 10551.54,9169.15 10551.54,9129 10562.54,9118 10705,9118 10820.24,9002.76 IC4.9@10854.51,9002.76
MCU_SOFT.TDI: IC1.A2 IC4.4 | length 259.6
  Top Layer w5: IC1.A2@10620.48,9175.65 10620.48,9163.82 10621.3,9163 10723.64,9163 10755.93,9130.71 IC4.4@10854.51,9130.71
MCU_SOFT.TDO: IC1.A1 IC4.3 R35.1 | length 222.4
  Top Layer w5: IC1.A1@10640.17,9175.65 10643.82,9172 10727.37,9172 10743.06,9156.3 10772.84,9156.3 IC4.3@10854.51,9156.3
MCU_SOFT.TMS: IC1.A5 IC4.8 | length 379.7
  Top Layer w5: IC1.A5@10561.43,9175.65 10561.43,9132 10566.43,9127 10708.73,9127 10807.38,9028.35 IC4.8@10854.51,9028.35
MD0: IC1.H3 R28.1 SDCARD1.7 | length 1472.4
  Top Layer w5: R28.1@9831.15,9142.42 v1(9857.58,9142.42) ; v1(10393.01,9239.02) 10512.01,9358.02 10512.01,9402.02 10519.01,9409.02 10542.01,9409.02 10552.01,9399.02 10552.01,9339.02 10566.9,9324.13 10590.11,9324.13 IC1.H3@10600.8,9313.44
  Bottom Layer w5: v1(9857.58,9142.42) 9999.42,9142.42 10027.83,9170.83 SDCARD1.7@10027.83,9298.18 10027.83,9329.02 10047.01,9329.02 10047.01,9369.02 10067.01,9389.02 10150.28,9389.02 10150.59,9389.33 10175.68,9389.33 10183.01,9382 10183.01,9217.99 10191,9210 10191,9168.02 10250,9109.02 10302.01,9109.02 10327.01,9134.02 10327.01,9173.02 v1(10393.01,9239.02)
MD1: IC1.J2 R29.1 SDCARD1.8 | length 4102.8
  Top Layer w3: IC1.J2@10620.48,9333.13 10630.37,9323.24 10646.66,9323.24
  Top Layer w5: R29.1@9742.34,9142.42 v1(9742.34,9180.34) ; 10646.66,9323.24 10694.5,9323.24 10708.01,9336.75 10708.01,9459 10699.01,9468 10699.01,9524.69 10672.01,9551.69 10672.01,9568.02 10683.01,9579.02 10713.01,9579.02 10717.01,9575.02 10717.01,9535.02 10733.01,9519.02 10743.01,9519.02 10752.01,9510.02 10752.01,9481.86 10737.01,9466.86 10737.01,9388.02 10755.01,9370.02 10863.98,9370.02 10872,9362 10872,9317 10883,9306 10926.02,9306 10957.01,9275.02 10957.01,9241.99 10962.02,9236.98 10987.98,9236.98 10997,9246 10997,9268 11003.82,9274.82 11094.18,9274.82 11104.8,9264.2 11104.8,9243 11109.8,9238 11144.75,9238 11153.73,9229.02 11230.01,9229.02 11281,9178.02 11281,9053.01 v1(11257.01,9029.02)
  Bottom Layer w5: SDCARD1.8@9963.86,9298.18 9963.86,9203.86 9952.02,9192.02 9754.02,9192.02 v1(9742.34,9180.34) 9710,9148 9710,9072.12 9724.1,9058.02 10064.4,9058.02 10075.4,9069.02 10287.55,9069.02 10399.01,8957.56 10399.01,8770.29 10430.28,8739.02 10690,8739.02 10729.39,8699.63 11121.05,8699.63 11167.01,8745.58 11167.01,8876.02 11181.01,8890.02 11181.01,8956.73 11195.28,8971 11261.99,8971 11267.01,8976.02 11267.01,9003.6 11257.01,9013.6 v1(11257.01,9029.02)
MD2: IC1.J1 R24.1 SDCARD1.9 | length 280.4
  Top Layer w5: IC1.J1@10640.01,9333.13 IC1.J1@10640.17,9333.13 10658.11,9333.13 v1(10679.01,9354.02) ; v1(10803,9428) 10820,9428 10826.95,9421.05 R24.1@10826.95,9392.8
  Bottom Layer w5: v1(10679.01,9354.02) 10679.01,9379.02 10689.01,9389.02 SDCARD1.9@10716.81,9389.02 ; SDCARD1.9@10716.81,9388.73 SDCARD1.9@10716.82,9389.02 ; v1(10803,9428) 10742,9428 10716.82,9402.82 SDCARD1.9@10716.82,9389.02
MD3: IC1.J3 R25.1 SDCARD1.1 | length 768.5
  Top Layer w5: v1(10572.01,9348.02) 10572.73,9348.02 10587.62,9333.13 IC1.J3@10600.8,9333.13 10603.01,9333.13 10603.01,9334.02 IC1.J3@10602.35,9334.68 ; v1(10909,9134) 10909,9172 10964.98,9227.98 10992,9227.98 11020.53,9256.51 R25.1@11037.01,9256.51
  Bottom Layer w5: v1(10572.01,9348.02) 10606.6,9348.02 10618.39,9336.23 SDCARD1.1@10618.39,9278.5 10618.39,9160.61 10645,9134 v1(10909,9134)
NetC1_1: C1.1 IC1.M17 L1.1 L2.1 | length 573.3
  Top Layer w3: 10299.03,9402.07 10315.32,9402.07 IC1.M17@10325.21,9392.18
  Top Layer w5: C1.1@9983.65,9213.21 10049.46,9279.02 ; L1.1@10027.93,9400.17 L2.1@10027.93,9322.43 10027.93,9300.55 10049.46,9279.02 ; 10299.03,9402.07 10263.06,9402.07 10184.01,9323.02 10184.01,9290.02 10173.01,9279.02 10049.46,9279.02
NetC6_1: C6.1 IC6.3 R40.1 R45.2 | length 259.4
  Top Layer w5: R45.2@10003.01,10174.58 R45.2@10000.91,10174.58 10000.91,10140.58 10011.97,10129.53 IC6.3@10064.36,10129.53 ; R40.1@10088.17,10174.58 10088.17,10153.34 IC6.3@10064.36,10129.53 ; C6.1@10133.55,10174.58 10133.55,10153.18 10109.9,10129.53 IC6.3@10064.36,10129.53
NetCN2_2: CN2.2 R19.1 | length 598
  Top Layer w5: CN2.2@11167.35,9898.13 11203.13,9898.13 11211.4,9906.4 11211.4,9963.08 11164.01,10010.47 11164.01,10175.02 11133.01,10175.02 11127.01,10181.02 11127.01,10227.02 11129.01,10229.02 11163.01,10229.02 11177.01,10215.02 11177.01,10191.02 11187.01,10181.02 11187.01,10140.12 11198.39,10128.73 R19.1@11198.39,10103.73
NetCN2_3: CN2.3 IC3.5 R20.1 | length 658.6
  Top Layer w5: IC3.5@10996.22,9361.98 11030.01,9361.98 11056.38,9388.36 R20.1@11090.15,9388.36 11090.15,9369.87 11112.01,9348.02 11112.01,9320.02 11116,9316.02 11154.02,9316.02 11178,9340 11302.77,9340 11305,9342.23 11305,9383.86 11301.86,9387 11274,9387 11252.98,9408.02 11179.22,9408.02 11167.35,9419.9 CN2.3@11167.35,9496.55
NetCN3_18: CN3.18 D3.2 | length 505.2
  Top Layer w12: CN3.18@11197.86,8941.59 11227.59,8941.59 11305.19,9019.19 11305.19,9309.19 11356.19,9360.19 D3.2@11356.19,9363.76
NetD3_1: D3.1 R37.2 | length 58.5
  Top Layer w12: R37.2@11212.36,9364 D3.1@11267.27,9363.76 D3.1@11263.67,9363.76
NetD4_1: D4.1 IC6.1 L3.2 | length 147.1
  Top Layer w5: L3.2@10064.37,10019.02 L3.2@10064.37,9991.56 10093.01,9991.55 10103.82,10002.37 D4.1@10144.06,10002.37
  Top Layer w12: L3.2@10064.36,10019.03 IC6.1@10064.36,10054.53
NetIC1_H16: IC1.H16 R8.1 | length 414.4
  Top Layer w5: R8.1@10186.37,9020.86 10186.37,9042.05 10254.01,9109.68 v1(10254.01,9149.02) v1@10255.01,9149.02 ; IC1.H16@10344.89,9313.44 10355.56,9313.44 10358,9311 10358,9294.02 v1(10382.01,9270.02)
  Bottom Layer w5: v1(10254.01,9149.02) 10285.01,9149.02 10372.01,9236.02 10372.01,9245.66 10382.01,9255.66 v1(10382.01,9270.02)
NetIC1_J16: IC1.J16 R1.1 | length 847.4
  Top Layer w5: R1.1@10274.93,9771.61 10274.93,9748.07 10283.98,9739.02 v1(10328.01,9739.02) ; IC1.J16@10344.89,9333.13 10361.87,9333.13 10375.98,9319.02 10447.55,9319.02 10492.01,9363.47 10492.01,9418.02 10502.01,9428.02 10532.02,9428.02 10533.01,9429.01 v1(10533.01,9449.02)
  Bottom Layer w5: v1(10328.01,9739.02) 10473.01,9739.02 10512.01,9700.02 10512.01,9578.02 10493.01,9559.02 10493.01,9515.29 10533.01,9475.29 v1(10533.01,9449.02)
NetIC1_J17: IC1.J17 R7.1 | length 485.2
  Top Layer w3: 10299.03,9343.02 10315.32,9343.02 IC1.J17@10325.21,9333.13
  Top Layer w5: R7.1@10097.57,9020.86 10152.46,9020.86 10229.01,9097.41 10229.01,9302.29 10269.73,9343.02 10299.03,9343.02
NetIC1_K18: IC1.K18 R2.1 | length 2230.5
  Top Layer w5: v1(10093.01,9049.02) 10116.12,9072.13 10116.93,9072.13 ; 10116.93,9072.95 10164.2,9072.95 10187.01,9095.75 10187.01,9198.43 10220.01,9231.43 10220.01,9306.02 10266.8,9352.81 IC1.K18@10305.52,9352.81 ; v1(10253.01,9649.02) 10253.01,9713.77 10259.18,9719.95 10344.74,9719.95 10354.63,9729.84 10354.63,9751.93 R2.1@10334.96,9771.61
  Bottom Layer w5: v1(10093.01,9049.02) 9720.37,9049.02 9701,9068.39 9701,9630.41 9772.61,9702.02 10102.97,9702.02 10133.97,9671.02 10183.4,9671.02 10205.4,9649.02 v1(10253.01,9649.02)
NetIC1_L17: IC1.L17 R3.1 | length 860.5
  Top Layer w3: 10299.03,9382.39 10315.32,9382.39 IC1.L17@10325.21,9372.5
  Top Layer w5: R3.1@10008.76,9020.86 9991.73,9020.86 9969.89,8999.02 9903.01,8999.02 9897.01,9005.02 9897.01,9082.01 9905.95,9090.95 10155.53,9090.95 10169.01,9104.42 10169.01,9205.89 10202.01,9238.89 10202.01,9314.02 10270.38,9382.39 10299.03,9382.39
NetIC1_L18: IC1.L18 R6.1 | length 665
  Top Layer w5: R6.1@9919.96,9019.02 R6.1@9919.96,9020.86 9919.96,9069 9932.9,9081.95 10159.25,9081.95 10178.01,9100.7 10178.01,9202.16 10211.01,9235.16 10211.01,9310.02 10273.49,9372.5 IC1.L18@10305.52,9372.5 IC1.L18@10305.53,9372.02
NetIC1_N17: IC1.N17 L2.2 | length 251.9
  Top Layer w3: 10299.03,9421.76 10315.32,9421.76 IC1.N17@10325.21,9411.87
  Top Layer w5: L2.2@10146.05,9322.43 10163.42,9322.43 10202.01,9361.02 10202.01,9407.92 10211.11,9417.02 10249.73,9417.02 10254.47,9421.76 10299.03,9421.76
NetIC1_P16: IC1.P16 R4.1 | length 1153.9
  Top Layer w5: v1(9789,9103) 9831.15,9060.85 R4.1@9831.15,9020.86 ; IC1.P16@10344.9,9431.55 10355.77,9420.67 10391.62,9420.67 10444.28,9368.02 v1(10464.01,9368.02)
  Bottom Layer w5: v1(9789,9103) 9847.02,9103 9861,9089.02 10293.01,9089.02 10303.01,9079.02 10353.01,9079.02 10383.01,9109.02 10383.01,9155.39 10440.64,9213.02 10440.64,9243.65 10452.01,9255.02 10452.01,9330.75 10464.01,9342.75 v1(10464.01,9368.02)
NetIC1_P17: IC1.P17 L1.2 | length 200.4
  Top Layer w3: 10299.03,9441.44 10315.32,9441.44 IC1.P17@10325.21,9431.55
  Top Layer w5: L1.2@10146.05,9400.17 10161.16,9400.17 10196.01,9435.02 10241.01,9435.02 10247.43,9441.44 10299.03,9441.44
NetIC1_T15: IC1.T15 R5.1 | length 225.8
  Top Layer w5: IC1.T15@10363.01,9470.92 IC1.T15@10364.58,9470.92 10364.58,9456.45 v1(10372.01,9449.02) ; v1(10372.01,9602.02) 10372.01,9634.36 R5.1@10372.01,9638.02
  Bottom Layer w5: v1(10372.01,9449.02) 10372.01,9481.32 10359.7,9493.63 10359.7,9558.58 10372.01,9570.89 v1(10372.01,9602.02)
NetIC3_1: IC3.1 R31.2 | length 73.5
  Top Layer w5: IC3.1@10911.57,9399.39 10911.57,9419.02 10932.71,9440.16 R31.2@10932.71,9464.13
NetIC3_4: IC3.4 R30.2 | length 76.8
  Top Layer w5: R30.2@10975.07,9256.51 10975.07,9279.02 10996.22,9300.16 IC3.4@10996.22,9324.58
NetIC4_19: IC4.19 R32.2 R33.2 | length 1060.5
  Top Layer w5: R33.2@11198.9,8686.23 11196.58,8683.91 11187,8674.33 11187,8636.73 11228.87,8594.86 11290,8594.86 v1@11290.14,8594.86 ; v1(11290,8595) v1@11290.14,8594.86 ; R32.2@11302.74,8563.75 11290.14,8576.35 v1@11290.14,8594.86
  Bottom Layer w5: v1(11122,9176) 11131.51,9166.49 11321.51,9166.49 11362,9126 11362,8620 11337,8595 v1(11290,8595)
NetIC5_2: IC5.2 R36.2 | length 1553.1
  Top Layer w5: IC5.2@10857.46,8852.07 10820.93,8852.07 10816.01,8856.99 10816.01,8881.01 10827.06,8892.06 10848.06,8892.06 10864,8908 10864,8929 10871,8936 10919.99,8936 v1(10937.01,8953.02) ; R36.2@11145.31,10103.73 11145.31,10099.02 11147.01,10099.02 11147.01,10073.02 11104.58,10030.59 11104.58,9677.44 v1(11187.01,9595.02)
  Bottom Layer w5: v1(10937.01,8953.02) 11033,9049.01 11033,9380 11058,9405 11058,9491.29 11161.73,9595.02 v1(11187.01,9595.02)
NetIC5_4: IC5.4 R38.2 | length 1734.2
  Top Layer w5: v1(10749,9026) 10749,9005.51 10753,9001.51 10782.63,9001.51 10807.01,8977.14 10807.01,8824.99 10831.11,8800.89 IC5.4@10857.46,8800.89 ; v1(11087.01,9659.02) 11087.01,9700.1 11095.58,9708.68 11095.58,10034.32 11127.01,10065.75 11127.01,10153.02 11133.01,10159.02 11145.31,10159.02 R38.2@11145.31,10156.37
  Bottom Layer w5: v1(10749,9026) 10765.98,9009.02 10883.28,9009.02 11000,9125.74 11000,9386.27 11031,9417.27 11031,9640 11050.02,9659.02 v1(11087.01,9659.02)
NetIC5_6: IC5.6 R39.2 | length 1744.2
  Top Layer w5: IC5.6@10857.46,8749.71 10932.71,8749.71 10947,8764 10947,8932 10957,8942 10957,8977 10948,8986 v1(10930,8986) ; R39.2@11145.31,10209.02 11145.31,10194.02 11150.31,10189.02 11166.01,10189.02 11173.01,10182.02 11173.01,10014.2 11222.01,9965.2 v1(11222.01,9668.02)
  Bottom Layer w5: v1(10930,8986) 10957.26,8986 11023.89,9052.63 11023.89,9056.91 11023.89,9384.71 11049,9409.82 11049,9495.01 v1(11222.01,9668.02)
NetIC5_8: IC5.8 R43.2 | length 338.6
  Top Layer w5: IC5.8@11075.97,8724.12 11144.89,8724.12 11157.01,8712 11157.01,8648.33 11117.01,8608.33 11117.01,8505.02 11133.01,8489.02 11133.01,8490.95 R43.2@11137.43,8490.95
NetIC5_10: IC5.10 R46.2 | length 427.5
  Top Layer w5: v1(11058.19,8631.65) 11033.59,8656.25 11033.59,8767 11041.89,8775.3 IC5.10@11075.97,8775.3 ; R46.2@11137.43,8542.12 11165.47,8542.12 11177.01,8553.66 v1(11177.01,8576.02)
  Bottom Layer w5: v1(11058.19,8631.65) 11168.4,8631.65 11177.01,8623.04 v1(11177.01,8576.02)
NetIC5_12: IC5.12 R47.2 | length 359.6
  Top Layer w5: IC5.12@11075.97,8826.48 11109.48,8826.48 11122,8839 11149,8839 11154,8834 11154,8806 11143,8795 11143,8756.81 11167.01,8732.81 11167.01,8644.19 11137.43,8614.62 R47.2@11137.43,8593.29 11137.44,8589.02 R47.2@11140.01,8589.02
NetLED1_B: LED1.B R38.1 | length 214.1
  Top Layer w5: LED1.B@10910.6,10194.87 11048.35,10194.87 11064.1,10179.12 11064.1,10169.64 11076.87,10156.87 11102.94,10156.87 R38.1@11102.94,10156.37
NetLED1_G: LED1.G R36.1 | length 196
  Top Layer w5: LED1.G@10910.6,10094.87 11040.47,10094.87 11049.34,10103.73 R36.1@11102.94,10103.73
NetLED1_R: LED1.R R39.1 | length 207.2
  Top Layer w5: LED1.R@10910.6,10244.87 11023.33,10244.87 11059.18,10209.02 R39.1@11102.94,10209.02
NetLED2_B: LED2.B R46.1 | length 184.8
  Top Layer w5: LED2.B@10910.6,8541.32 10993.01,8541.32 10993.81,8542.12 R46.1@11095.07,8542.12
NetLED2_G: LED2.G R43.1 | length 205.3
  Top Layer w5: LED2.G@10910.6,8441.32 11031.32,8441.32 11080.46,8490.46 R43.1@11095.07,8490.46 ; R43.1@11095.07,8490.95 11095.07,8490.84 R43.1@11095.08,8490.46
NetLED2_R: LED2.R R47.1 | length 185.3
  Top Layer w5: LED2.R@10910.6,8591.32 10993.01,8591.32 10994.97,8593.29 R47.1@11095.07,8593.29
PROD_ID: D1.2 IC1.B1 R13.1 R14.1 | length 2578.5
  Top Layer w5: IC1.B1@10640.17,9195.33 10656.33,9195.33 10662,9201 v1(10714,9201) ; v1(10950,9162) 10950,9187.54 10972.44,9209.98 10999.46,9209.98 11014.48,9225 11145.02,9225 v1(11161.01,9209.02) ; R14.1@11239.28,10209.02 R13.1@11292.86,10209.02 11327.81,10174.06 D1.2@11327.81,10151.96 11327.81,10123.83 v1(11307.01,10103.02)
  Bottom Layer w5: v1(10714,9201) 10753,9162 v1(10950,9162) ; v1(11161.01,9209.02) 11143.01,9227.02 11143.01,9396.29 11286.19,9539.48 11286.19,9748.32 11275.5,9759.02 11124.01,9759.02 11093.01,9728.02 10944,9728.02 10940.26,9731.76 10940.26,9790.59 10904.01,9826.84 10904.01,10130.94 10915.08,10142.02 11168.66,10142.02 11190.66,10120.02 11290.01,10120.02 v1(11307.01,10103.02)
RESETN: IC1.T14 IC4.1 IC7.2 R41.1 | length 3735
  Top Layer w5: R41.1@9743,8899.97 v1(9743,8950) ; v1(10147.01,9043.02) 10210.01,9106.02 v1(10210.01,9190.02) ; IC1.T14@10383.01,9470.92 IC1.T14@10384.26,9470.92 10396.84,9458.34 10396.84,9455.18 v1(10412.01,9440.02) ; v1(10687.01,8715.02) 10663.01,8739.02 10663.01,8829.43 10678.78,8845.2 IC7.2@10697.08,8845.2 ; v1(10691,8885) 10697.08,8878.92 IC7.2@10697.08,8845.2 ; IC7.2@10695.14,8847.14 IC7.2@10697.08,8845.2 ; IC4.1@10854.51,9207.48 10886.48,9207.48 10909,9230 v1(10909,9281) ; v1(10951,9129) 10983,9129 10995,9117 v1(10995,9081)
  Bottom Layer w5: v1(9743,8950) 9707,8950 9701,8956 9701,9029.04 9711.98,9040.02 10064.4,9040.02 10080.42,9024 10127.99,9024 v1(10147.01,9043.02) 10176.47,9043.02 10187.35,9032.14 10187.35,8969.16 10198.18,8958.34 10238.52,8958.34 10250.2,8970.02 10361.09,8970.02 10381.01,8950.11 10381.01,8762.03 10443.41,8699.63 10468.86,8699.63 10499.25,8730.02 10643,8730.02 10658,8715.02 10666.12,8715.02 10667.36,8713.78 ; v1(10210.01,9190.02) 10241.28,9190.02 10249.28,9198.02 10308.55,9198.02 10352.01,9241.47 10352.01,9348.02 10387.01,9383.02 10387.01,9415.02 v1(10412.01,9440.02) ; 10667.36,8715.02 v1(10687.01,8715.02) ; v1(10691,8885) 10688,8882 10579,8882 10563,8898 10544,8898 10498.01,8852.01 10498.01,8810.06 10505.05,8803.02 10708.75,8803.02 10776.75,8871.02 10881.25,8871.02 10894.25,8858.02 10930.02,8858.02 10942,8870 10942,8901.73 10898,8945.73 10898,8998.29 10937.71,9038 10983.8,9038 10995,9049.2 v1(10995,9081) ; v1@10911,9283 10971,9223 10971,9149 v1(10951,9129)
SOFT.TCK: CN3.12 IC4.11 | length 167.9
  Top Layer w5: IC4.11@11078.92,8977.17 11145.17,8977.17 11153.01,8985.01 11153.01,9027.01 11162.08,9036.08 CN3.12@11197.86,9036.08
SOFT.TDI: CN3.3 IC4.16 | length 172.7
  Top Layer w5: IC4.16@11078.92,9105.12 11133.39,9105.12 11160,9131.73 11160,9170 11167.82,9177.82 CN3.3@11197.86,9177.82 ; CN3.3@11203.01,9177.82 CN3.3@11203.01,9179.02
SOFT.TDO: CN3.2 IC4.17 | length 175
  Top Layer w5: IC4.17@11078.92,9130.71 11118,9130.71 11122.71,9126 11141.54,9126 11151,9135.46 11151,9180 11160.02,9189.02 11166.63,9189.02 11171.17,9193.56 CN3.2@11197.86,9193.56
SOFT.TMS: CN3.11 IC4.12 | length 155.7
  Top Layer w5: IC4.12@11078.92,9002.76 11137.76,9002.76 11144.01,9009.01 11144.01,9037.01 11158.83,9051.83 CN3.11@11197.86,9051.83
SYS_RSTN: IC7.3 JTAG1.5 R44.1 | length 988
  Top Layer w5: JTAG1.5@10078.38,8629.21 10078.38,8694.02 10104.38,8720.02 10180.01,8720.02 10214,8686.02 10214,8567 10225.96,8555.04 10301.5,8555.04 10314.29,8567.83 10314.29,8776.3 10342.01,8804.02 10490.01,8804.02 10510.01,8824.02 ; 10510.01,8824.03 10512.01,8826.03 R44.1@10528.81,8826.03 10553.01,8826.03 10572.18,8845.2 IC7.3@10610.47,8845.2
TCK: IC1.V4 JTAG1.3 R15.1 | length 3444
  Top Layer w5: JTAG1.3@9978.38,8629.21 9978.38,8694.02 9983.38,8699.02 10017.01,8699.02 10037.01,8719.02 10037.01,8903.02 10063.01,8929.02 10375.73,8929.02 10401.6,8954.89 10448.87,8954.89 10472.49,8978.5 R15.1@10508.88,8978.5 10508.88,8966.02 10517.01,8957.89 v1(10517.01,8938.02) ; IC1.V4@10581.01,9509.02 10581.11,9509.02 IC1.V4@10581.11,9510.29 ; IC1.V4@10581.01,9510.29 10581.01,9532.47 10592.01,9543.47 10592.01,9557.29 10590.01,9559.29 v1@10590.01,9569.68
  Top Layer w12: v1@10590.01,9569.68 v1(10590.01,9579.02)
  Bottom Layer w5: v1(10517.01,8938.02) 10517.01,8912 10525,8904.01 10525,8893 10489.01,8857.01 10489.01,8806.33 10501.32,8794.02 10712.48,8794.02 10767.48,8849.02 10949,8849.02 10994,8894.02 10994,8997.29 11042,9045.29 11042,9250.73 11051,9259.73 11051,9260 11055,9264 11117.9,9264 11117.95,9263.95 11134.01,9280.01 11134.01,9400.02 11277.19,9543.21 11277.19,9744.59 11271.77,9750.02 11127.73,9750.02 11096.73,9719.02 10913.01,9719.02 10753.01,9559.02 10720.01,9559.02 10700.01,9539.02 10623.01,9539.02 10606.61,9555.41 10606.61,9562.41 v1(10590.01,9579.02)
TDI: IC1.T5 JTAG1.1 R12.1 | length 1583
  Top Layer w5: JTAG1.1@9878.38,8629.21 9878.38,8751.13 9932.4,8805.15 9932.4,8919.96 9961.46,8949.02 10323.67,8949.02 10330.03,8955.38 10330.03,8969.64 10338.89,8978.5 ; v1(10292.01,9129.02) 10292.01,9070.02 10327.01,9035.02 10327.01,8990.38 10338.89,8978.5 ; R12.1@10366.69,8978.5 10338.89,8978.5 ; v1(10383.01,9299.02) 10440.28,9299.02 10502.01,9360.75 10502.01,9408.02 10513.01,9419.02 10543.01,9419.02 10552.01,9428.02 10552.01,9461.5 IC1.T5@10561.43,9470.92
  Bottom Layer w5: v1(10292.01,9129.02) 10243.01,9129.02 10227.01,9145.02 10227.01,9163.02 10253.01,9189.02 10312.28,9189.02 10361.01,9237.75 10361.01,9296.01 10364.02,9299.02 v1(10383.01,9299.02)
